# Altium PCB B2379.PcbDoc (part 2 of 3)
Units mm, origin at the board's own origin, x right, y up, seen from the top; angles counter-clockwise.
Board outline 50 x 95 mm, 4 copper layers (Top Layer 1 Signal, Layer 2, Layer 3, Bottom Layer 4 Signal), stack 1.536 mm thick; 177 components, 121 nets, 523 pads, 969 vias.
Unrouted connection lines stored in the file: 25.
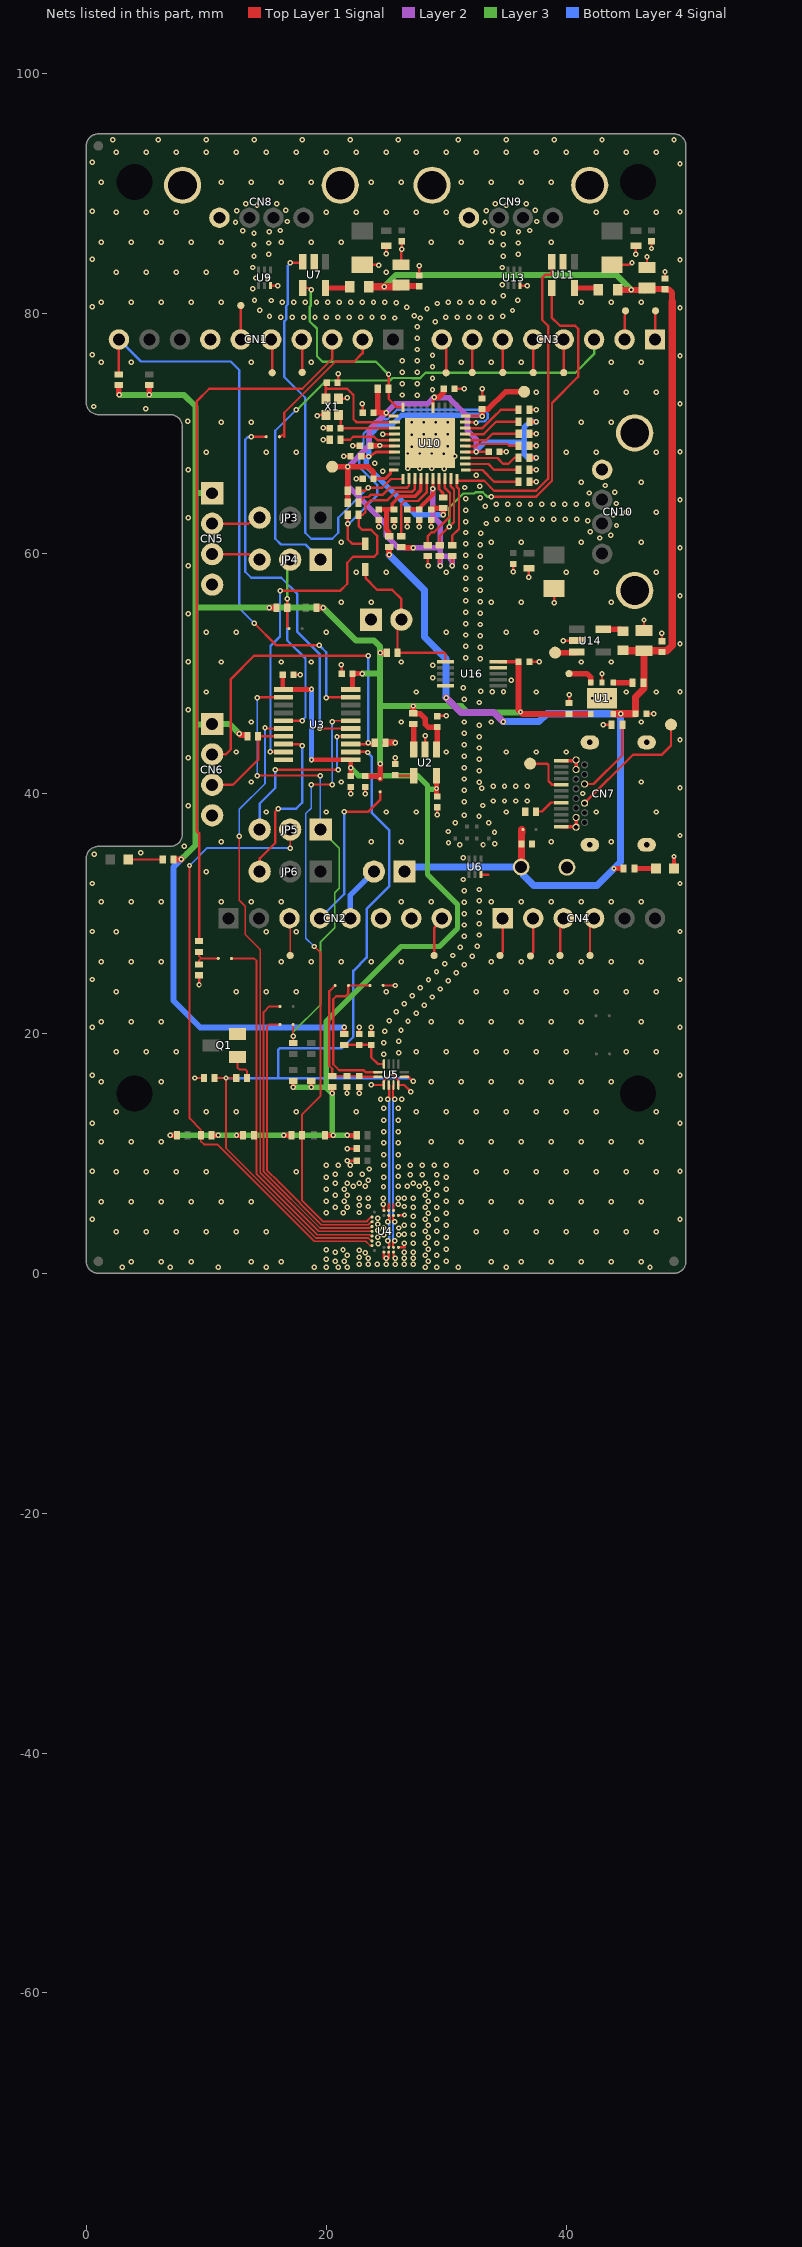
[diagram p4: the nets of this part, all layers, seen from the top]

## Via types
v1: diameter 0.45, hole 0.2, Top Layer 1 Signal to Bottom Layer 4 Signal, tented both sides, 933 vias
v2: diameter 0.45, hole 0.2, Top Layer 1 Signal to Bottom Layer 4 Signal, tented bottom, 24 vias
v3: diameter 0.45/0/0/0.45 (per signal layer), hole 0.2, Top Layer 1 Signal to Bottom Layer 4 Signal, tented both sides, 12 vias

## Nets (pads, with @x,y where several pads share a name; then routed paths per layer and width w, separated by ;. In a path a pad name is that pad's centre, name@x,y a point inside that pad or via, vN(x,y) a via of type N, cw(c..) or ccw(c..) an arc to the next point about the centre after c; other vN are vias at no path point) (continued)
+1V8: C4.2 C7.1 C9.2 R3.1 R17.2 R19.2 R20.2 R24.1 R35.2 R36.2 R37.2 R39.2 U2.5 U3.1 U3.11 | length 83.4
  Top Layer 1 Signal w0.4: v1(7,11.5) R35.2@7.55,11.5 ; R36.2@10.45,11.5 v1(11,11.5) ; v1(12.525,11.5) R3.1@13.08,11.5 ; C9.2@16.375,49.9 16.375,48.675 18.736,48.675 18.761,48.7 v1(18.775,48.7) ; v1(16.465,11.5) R37.2@17.093,11.5 ; v1(17.25,15.5) R20.2@17.25,16.05 ; v1(18.75,15.5) R17.2@18.75,16.05 ; v1(18.775,42.825) U3.11@22.05,42.825 v1(22.05,42.138) C7.1@22.05,41.45 ; R39.2@19.923,11.466 19.958,11.5 v1(20.575,11.5) ; v1(20.5,15) R19.2@20.5,15.55 ; v1(21.75,11.5) R24.1@22.55,11.5
  Top Layer 1 Signal w0.45: U2.5@29.2,41.475 v1(29.2,40.425) 29.2,39.785 C4.2@29.25,39.755
  Layer 3 w0.45: v1(7,11.5) v1(21.75,11.5) ; v1(17.25,15.5) v1(18.75,15.5) 20,15.5 ; v1(20.575,11.5) 20.575,11.514 20.5,11.589 v1(20.5,15) 20,15.5 ; v1(22.05,42.138) 22.688,41.5 27.619,41.5 28.444,40.675 28.444,40.363 ; v1(29.2,40.425) 29.186,40.425 29.124,40.363 28.444,40.363 ; 20,15.5 20,21 26.25,27.25 29.435,27.25 30.948,28.764 30.948,30.745 28.444,33.25 28.444,40.363
  Bottom Layer 4 Signal w0.45: v1(18.775,42.825) v1(18.775,48.7)
+3V3: C2.2 C3.2 C6.2 C8.2 C43.2 CN5.1 CN6.1 R2.1 R7.1 R9.2 R10.2 R11.2 R12.2 R16.2 R18.2 R58.2 R59.2 R60.2 U1.4 U2.1 U3.20 U16.10 | length 146.7
  Top Layer 1 Signal w0.3: U16.10@34.35,51 C43.2@36.05,51
  Top Layer 1 Signal w0.4: R18.2@21.5,19.95 v1(21.5,20.5) ; U3.20@22.05,48.675 22.2,48.675 C8.2@22.2,50 v1(23,50)
  Top Layer 1 Signal w0.45: R11.2@2.72,74.05 2.72,73.28 v1(2.75,73.25) ; v1(5.25,73.25) 5.26,73.26 R12.2@5.26,74.05 ; v1(15.25,55.5) R58.2@15.85,55.5 ; R59.2@19.2,55.5 v1(19.75,55.5) ; C6.2@23.25,41.45 24.3,41.45 R2.1@24.5,41.25 v1(24.5,42.5) ; v1(24.5,51.75) R60.2@25.05,51.75 ; v1(27.25,47.299) R7.1@27.25,46.7 27.28,46.67 27.83,46.67 28.211,46.289 28.25,46.25 28.25,45.784 28.514,45.52 29.22,45.52 C3.2@29.25,45.55 29.25,45.52 29.25,43.725 U2.1@29.2,43.675
  Top Layer 1 Signal w0.5: R16.2@7.275,34.5 7.275,34.515 7.28,34.52 7.92,34.52 v1(7.925,34.525) ; v1(12.75,45) 12.87,44.88 13.395,44.88 13.425,44.85 R9.2@13.425,44.775 ; R10.2@24.949,44.25 v1(25.75,44.25) ; C43.2@36.05,51 36.05,46.95 v1(36.2,46.8) 36.35,46.65 C2.2@40.25,46.65 ; C2.2@40.263,46.65 U1.4@42.05,46.65
  Layer 3 w0.5: v1(2.75,73.25) v1(5.25,73.25) 8.14,73.25 9.102,72.288 9.102,35.701 8.399,34.998 8.398,34.998 v1(7.925,34.525) ; 9.223,45.75 10.44,45.75 CN6.1@10.5,45.81 11.94,45.81 v1(12.75,45) ; 9.223,65.046 10.494,65.046 CN5.1@10.5,65.04 ; 9.223,55.5 v1(15.25,55.5) v1(19.75,55.5) 22.5,52.75 24,52.75 24.5,52.25 v1(24.5,51.75) 24.5,50 ; v1(23,50) 24.5,50 ; v1(24.5,42.5) 24.5,44.125 ; v1(25.75,44.25) 24.625,44.25 24.5,44.125 ; v1(36.2,46.8) 36.15,46.75 31.814,46.75 31.265,47.299 v1(27.25,47.299) 24.502,47.299 24.5,47.297 ; 24.5,44.125 24.5,47.297 ; 24.5,47.297 24.5,50
  Bottom Layer 4 Signal w0.5: v1(7.925,34.525) 7.25,33.85 7.25,22.75 9.5,20.5 v1(21.5,20.5)
+5V: C1.2 C10.2 C17.2 C18.2 C21.2 C22.2 C39.2 C40.2 JP1.1 L1.1 L2.1 L3.1 R1.1 R14.2 R21.2 R57.1 TP18.1 U1.6 | length 138.1
  Top Layer 1 Signal w0.45: v1(44,33.75) R21.2@44.8,33.75
  Top Layer 1 Signal w0.5: v1(25.25,59.9) R57.1@25.25,60.55 ; C17.2@26.15,82.3 C18.2@27.75,82.3 ; L2.1@44.3,82 v1(45.45,82) C21.2@46.6,82 ; C21.2@46.75,82.15 46.85,82.05 C22.2@48.25,82.05 48.255,82.045 48.555,82.045 48.848,81.752 48.848,81
  Top Layer 1 Signal w0.6: L1.1@23.55,82.25 v1(24.825,82.25) 26.1,82.25 C17.2@26.15,82.3 ; TP18.1@36.25,33.875 36.275,33.9 C10.2@36.275,35.8 36.275,36.7 36.3,36.725 R14.2@36.3,37 ; U1.6@43.95,46.65 v1(44.55,46.65) 45.1,46.65 ; L3.1@44.75,51.95 44.8,51.9 C39.2@46.5,51.9 ; 45.101,46.65 C1.2@45.8,46.65 45.8,48.05 46.5,48.75 C39.2@46.5,51.9 ; C21.2@46.6,82 C21.2@46.75,82.15 ; 48.848,81 48.848,52.348 48.4,51.9 C39.2@46.5,51.9
  Layer 2 w0.6: v1(30,48) 31.25,46.75 34,46.75 v1(34.75,46)
  Layer 3 w0.5: v1(24.825,82.25) 25.825,83.25 44.2,83.25 v1(45.45,82)
  Bottom Layer 4 Signal w0.6: v1(25.25,59.9) 28.191,56.959 28.191,53.059 30,51.25 v1(30,48) ; JP1.1@26.52,33.5 26.895,33.875 TP18.1@36.25,33.875 36.403,33.722 36.403,33.222 37.3,32.325 42.575,32.325 v1(44,33.75) 44.55,34.3 v1(44.55,46.65) 38.4,46.65 37.75,46 v1(34.75,46)
CC1_3: CN7.A5 R13.2 | length 2.4
  Top Layer 1 Signal w0.19: R13.2@37.5,38.5 38,38.5 38.75,39.25 CN7.A5@39.59,39.25
CC2_3: CN7.B5 R15.2 | length 6.7
  Top Layer 1 Signal w0.2: CN7.B5@41.55,40.8 42.3,40.8 44.7,43.2 R15.2@44.7,45.75
CFG_SCL_1V8_ST60_3: R26.2 U4.E1 | length 23.7
  Top Layer 1 Signal w0.15: 16,20.75 15.25,20.75 15.054,20.554 15.054,8.599 16.076,7.576 19.599,4.054 23.516,4.054 23.689,4.227 23.725,4.227 23.798,4.3 U4.E1@23.825,4.3
CFG_SDA_1V8_ST60_3: R27.2 U4.F1 | length 25.9
  Top Layer 1 Signal w0.15: R27.2@16.15,22.25 15.25,22.25 14.777,21.777 14.777,8.484 19.484,3.777 23.639,3.777 23.689,3.827 23.725,3.827 23.798,3.9 U4.F1@23.825,3.9
eUSB_ST60_3_N: U4.C5 U4.L5 U5.3 | length 14.3
  Top Layer 1 Signal w0.19: v3@25.573,2.694 25.573,2.211 U4.L5@25.615,2.17 ; v3@25.573,4.3 25.573,4.79 25.614,4.83 U4.C5@25.615,4.83 ; U5.3@25.615,15.7 ccw(c25.615,15.659) 25.573,15.659 25.573,14.63 ccw(c25.704,14.63) v3(25.704,14.5)
  Bottom Layer 4 Signal w0.19: v3@25.574,2.7 25.574,14.37 cw(c25.704,14.37) v3(25.704,14.5)
  other v3: 25.704,2.7 25.704,4.3
eUSB_ST60_3_P: U4.C4 U4.L4 U5.2 | length 14.2
  Top Layer 1 Signal w0.19: v3(25.127,14.5) ccw(c25.127,14.63) 25.257,14.63 25.257,15.659 ccw(c25.215,15.659) U5.2@25.215,15.7 ; U4.L4@25.215,2.17 25.215,2.212 25.256,2.254 v3@25.256,2.694 ; U4.C4@25.215,4.83 25.216,4.83 25.257,4.79 v3@25.257,4.3
  Bottom Layer 4 Signal w0.19: v3(25.127,14.5) cw(c25.127,14.37) 25.257,14.37 v3@25.257,2.743
  other v3: 25.127,2.7 25.127,4.3
EXT_RX_3V3_4: CN5.3 JP4.3 | length 4.2
  Top Layer 1 Signal w0.2: CN5.3@10.5,59.96 13.554,59.96 14.014,59.5 JP4.3@14.46,59.5
EXT_SCL_1V8_4: JP5.3 U3.14 | length 14.8
  Top Layer 1 Signal w0.2: v1(15.75,42) v1(21,42) ; v1(20.902,44.725) 20.952,44.775 U3.14@22.05,44.775
  Bottom Layer 4 Signal w0.2: JP5.3@14.46,37 14.46,39.171 15.75,40.461 v1(15.75,42) ; v1@20.927,44.7 v1(20.902,44.725) 20.902,42.098 v1(21,42)
EXT_SCL_3V3_4: CN6.3 R9.1 U3.7 | length 8.8
  Top Layer 1 Signal w0.2: CN6.3@10.5,40.73 12.23,40.73 14.325,42.825 R9.1@14.325,44.775 U3.7@16.45,44.775
EXT_SDA_1V8_4: JP6.3 U3.8 | length 14.4
  Top Layer 1 Signal w0.2: JP6.3@14.46,33.5 14.471,33.511 14.471,34.608 15.75,35.887 15.75,38.5 v1(16,38.75) ; U3.8@16.45,44.125 17.875,44.125 v1(18,44)
  Bottom Layer 4 Signal w0.2: v1(16,38.75) 17.5,38.75 18,39.25 v1(18,44)
EXT_SDA_3V3_4: CN6.2 R10.1 U3.13 | length 29.1
  Top Layer 1 Signal w0.2: CN6.2@10.5,43.27 11.63,43.27 12.05,43.69 12.05,49.55 14,51.5 v1(23.5,51.5) ; U3.13@22.05,44.125 23.924,44.125 R10.1@24.049,44.25
  Bottom Layer 4 Signal w0.2: v1(23.5,44.25) v1(23.5,51.5)
EXT_TX_3V3_4: CN5.2 JP3.3 | length 4.2
  Top Layer 1 Signal w0.2: CN5.2@10.5,62.5 13.518,62.5 14.018,63 JP3.3@14.46,63
GND: C1.1 C2.1 C3.1 C4.1 C5.1 C6.1 C7.2 C8.1 C9.1 C10.1 C11.1 C12.2 C13.2 C14.2 C15.1 C16.2 C17.1 C18.1 C19.1 C20.1 C21.1 C22.1 C23.1 C24.1 C25.1 C26.1 C27.1 C28.1 C29.1 C30.1 C31.1 C32.1 C33.1 C34.1 C35.1 C36.1 C37.1 C38.1 C39.1 C40.1 C41.1 C42.1 C43.1 CN1.7 CN2.6 CN2.7 CN5.4 CN6.4 CN7.A1 CN7.A12 CN7.B1 CN7.B12 CN7.SH1 CN7.SH2 CN7.SH3 CN7.SH4 CN8.4 CN8.5 CN8.6 CN9.4 CN9.5 CN9.6 CN10.4 CN10.5 CN10.6 H1.1 H2.1 H3.1 H4.1 JP2.1 LD2.2 Q1.2 R6.1 R13.1 R15.1 R28.2 R38.1 R42.1 R43.1 R44.1 R45.1 R46.1 R47.1 R54.2 TP20.1 U1.2 U1.EP U2.2 U3.10 U4.A3 U4.A4 U4.A5 U4.C6 U4.L6 U4.N3 U4.N4 U4.N5 U5.1 U5.4 U6.3 U7.2 U8.2 U9.3 U10.34 U10.41 U11.2 U12.2 U13.3 U14.2 U15.2 U16.5 U16.9 X1.2 X1.4 | length 61.5
  Top Layer 1 Signal w0.2: v1(9.035,16.285) R38.1@9.8,16.285 ; v1(9.4,24.052) R6.1@9.4,24.852 ; U9.3@15.35,82.35 v1@15.95,82.35 ; C9.1@17.275,49.9 v1(17.825,49.9) ; v1(19.25,71.5) 19.325,71.575 X1.4@19.975,71.575 ; v1(19.75,69.5) R54.2@20.3,69.5 ; v1(19.75,70.5) 19.78,70.47 C25.1@20.3,70.47 ; C26.1@20.95,74.25 21,74.3 v1(21,75) ; X1.2@21.025,72.925 21.675,72.925 v1(21.75,73) ; v1(21.25,50.75) 21.25,50.682 21.3,50.632 C8.1@21.3,50 ; v1(21.465,68.134) 21.474,68.125 C29.1@22.025,68.125 ; v1(21.735,15) C12.2@21.735,15.55 ; v1(21.75,9.375) C15.1@22.55,9.375 ; v1(21.75,10.4) C16.2@22.55,10.4 ; v1@22,40 22.05,40.05 C7.2@22.05,40.55 ; v1(22.225,69) C30.1@22.8,69 ; v1(22.5,66.25) C31.1@23.05,66.25 ; v1(22.75,15) C14.2@22.75,15.55 ; C13.2@22.75,19.95 v1(22.75,20.525) ; v1(23,72.5) 23,72.432 23.05,72.382 C32.1@23.05,71.75 ; C19.1@23,84.1 23.755,84.1 24.25,84.1 cw(c24.25,83.9) v1(24.38,84.052) ; v1(23.25,40) C6.1@23.25,40.55 ; C11.1@23.75,19.95 v1(23.75,20.525) ; v1(23.765,15.708) 24.314,15.7 ccw(c24.316,15.9) 24.316,15.7 U5.1@24.815,15.7 24.815,16.062 25.08,16.327 25.09,16.327 v1(25.474,16.712) 25.888,16.298 25.888,16.24 26.015,16.113 U5.4@26.015,15.7 26.515,15.7 v1(27.065,15.15) ; v1(24.375,62.25) 24.383,62.258 24.383,62.792 C38.1@24.39,62.8 ; v1(24.708,69.975) U10.34@25.7,69.975 ; R28.2@24.75,24 v1(25.75,24) ; v1@24.815,1.241 U4.N3@24.815,1.77 ; U4.A3@24.815,5.23 v1@24.815,5.759 ; v1(25,85) U8.2@25,85.675 ; v1@25.215,1.241 U4.N4@25.215,1.77 ; U4.A4@25.215,5.23 25.215,5.758 ; v1@25.615,1.241 U4.N5@25.615,1.77 ; U4.A5@25.615,5.23 25.615,5.758 ; C37.1@25.65,62.8 25.662,62.788 25.662,62.263 v1(25.675,62.25) ; C5.1@25.75,42.45 v1(25.75,43) ; U4.L6@26.015,2.17 26.543,2.17 ; U4.C6@26.015,4.83 v1@26.543,4.83 ; C17.1@26.25,84.1 26.25,85.257 26.3,85.307 v1(26.3,85.375) C20.1@26.3,86.05 ; v1(26.75,62.25) C35.1@26.75,62.8 ; v1(27.75,62.25) C36.1@27.75,62.8 ; C18.1@27.75,83.2 v1(27.75,84) ; U2.2@28.25,43.675 v1(28.25,44.825) ; R44.1@28.475,59.8 28.475,59.025 v1(28.5,59) ; v1(28.75,62.25) C27.1@28.75,62.8 ; v1(29.25,38.23) C4.1@29.25,38.855 ; C3.1@29.25,46.45 29.3,46.5 v1(30,46.5) ; C33.1@30.7,73.75 v1(31.5,73.75) ; U6.3@32.896,33.24 33.495,33.24 33.496,33.241 ; C28.1@33,72.95 v1(33,73.75) ; C34.1@34.45,68.5 v1(35,68.5) ; v1(35.6,58.5) C42.1@35.6,59.15 ; U13.3@36.15,82.35 36.746,82.35 v1(36.75,82.354) ; v1(36.9,58.025) U15.2@36.9,58.775 ; C43.1@36.95,51 v1(37.75,51) ; R45.1@36.95,66 v1(37.5,66) ; R42.1@36.95,67 v1(37.5,67) ; R46.1@36.95,69 v1(37.5,69) ; R47.1@36.95,72 v1(37.5,72) ; R43.1@36.954,70.003 37.497,70.003 v1(37.5,70) ; v1(39,55.925) C41.1@39,57.1 ; v1(39.775,52.75) U14.2@40.9,52.75 ; C2.1@40.25,47.55 v1(40.25,48.25) ; CN7.B12@40.79,37.25 CN7.B12@40.84,37.2 ; U1.2@43,49.25 v1(43,50) ; v1(43.1,45.75) R15.1@43.8,45.75 ; C23.1@43.825,84.1 45.282,84.1 45.432,84.25 v1(45.5,84.25) ; v1(45.825,84.975) U12.2@45.825,85.675 ; C39.1@46.5,53.6 v1(46.5,54.475) ; C1.1@46.7,46.65 v1(47.325,46.65) ; C21.1@46.75,83.85 v1(46.75,84.75) ; v1(47.125,85.45) C24.1@47.125,86.05 ; v1(47.975,53.375) 48,53.35 C40.1@48,52.7 ; C22.1@48.25,82.95 v1(48.25,83.5)
  Top Layer 1 Signal w0.3: CN7.A1@39.59,37.25 CN7.B12@40.79,37.25 ; CN7.A12@39.59,42.75 40.79,42.75 CN7.B1@40.84,42.8 CN7.B1@40.84,42 ; CN7.B12@40.84,37.2 CN7.B12@40.84,38 ; LD2.2@49,33.75 v1(49,34.75)
  other v1: 3,0.5 7,0.5 11,0.5 15,0.5 19,0.5 19.998,0.505 21,0.5 21.75,0.5 28.25,0.5 29.215,0.5 31,0.5 35,0.5 47,0.5 22.75,0.75 23.5,0.75 24.25,0.75 25,0.75 25.75,0.75 26.5,0.75 27.25,0.75 3.758,0.967 6.258,0.967 8.758,0.967 13.758,0.967 16.258,0.967 33.758,0.967 36.258,0.967 38.758,0.967 41.258,0.967 43.758,0.967 46.258,0.967 20.75,1 21.5,1 28.5,1 30,1 20,1.169 23.5,1.25 25,1.25 25.75,1.25 26.5,1.25 27.25,1.25 22.75,1.35 21.75,1.5 28.25,1.5 29.215,1.5 23.248,1.705 20.75,1.75 26.5,1.75 27.25,1.75 22.75,1.925 19.998,1.953 21.4,1.95 28.5,2 30,2 24.325,2.475 26.5,2.5 27.25,2.5 28.25,2.5 29.215,2.508 24.3,3 28.5,3 30,3 24.8,3.2 26.05,3.2 26.5,3.25 27.25,3.25 2.508,3.467 5.008,3.467 7.508,3.467 10.008,3.467 12.508,3.467 15.008,3.467 32.508,3.467 35.008,3.467 37.508,3.467 40.008,3.467 42.508,3.467 45.008,3.467 47.508,3.467 28.25,3.5 29.215,3.5 24.3,3.6 24.805,3.779 26.045,3.779 26.5,4 27.25,4 28.5,4 30,4 24.3,4.1 0.5,4.5 28.25,4.5 29.215,4.5 49.5,4.5 24.3,4.6 27.25,4.75 26.532,4.865 28.5,5 30,5 19.998,5.042 21.425,5.05 22.748,5.073 20.75,5.5 21.75,5.5 27.25,5.5 28.25,5.5 29.215,5.5 23.5,5.575 26.5,5.575 22.75,5.675 24.75,5.75 26.025,5.75 1.258,5.967 3.758,5.967 6.258,5.967 8.758,5.967 11.258,5.967 13.758,5.967 31.258,5.967 33.758,5.967 36.258,5.967 38.758,5.967 41.258,5.967 43.758,5.967 46.258,5.967 20,6 21.5,6 28.5,6 30,6 22.75,6.25 23.5,6.25 24.75,6.25 26.025,6.25 26.5,6.25 27.25,6.25 20.75,6.5 21.75,6.5 28.25,6.5 29.215,6.5 20,7 21.5,7 28.5,7 30,7 24.775,7.225 22.25,7.25 23.25,7.25 26.025,7.25 26.75,7.25 27.75,7.25 20.75,7.5 21.75,7.5 22.75,7.5 27.25,7.5 28.25,7.5 29.215,7.5 23.5,7.75 20,8 24.8,8 30,8 26.025,8.1 27,8.225 28,8.225 29.215,8.225 20.75,8.25 22,8.25 23,8.25 2.508,8.467 5.008,8.467 7.508,8.467 10.008,8.467 17.508,8.467 32.508,8.467 35.008,8.467 37.508,8.467 40.008,8.467 42.508,8.467 45.008,8.467 47.508,8.467 0.5,8.5 49.5,8.5 23.6,8.7 26.025,8.9 20,9 21,9 22,9 24.8,9 27,9 28,9 29,9 30,9 24.8,9.9 26.025,9.9 24.8,10.9 26.025,10.9 1.258,10.967 3.758,10.967 6.258,10.967 28.758,10.967 31.258,10.967 33.758,10.967 36.258,10.967 38.758,10.967 41.258,10.967 43.758,10.967 46.258,10.967 24.8,11.8 26.025,11.8 0.5,12.5 49.5,12.5 24.8,12.75 26.025,12.75 2.508,13.467 7.508,13.467 10.008,13.467 12.508,13.467 17.508,13.467 22.508,13.467 27.508,13.467 30.008,13.467 32.508,13.467 35.008,13.467 37.508,13.467 40.008,13.467 42.508,13.467 47.508,13.467 24.8,13.75 26.025,13.75 24.53,14.5 26.3,14.5 1.258,15.967 6.258,15.967 28.758,15.967 31.258,15.967 33.758,15.967 36.258,15.967 38.758,15.967 41.258,15.967 43.758,15.967 0.5,16.5 49.5,16.5 24.795,18.273 26.035,18.391 2.508,18.467 5.008,18.467 7.508,18.467 27.508,18.467 30.008,18.467 32.508,18.467 35.008,18.467 37.508,18.467 40.008,18.467 45.008,18.467 47.508,18.467 24.795,19.223 26.035,19.341 24.899,20.167 26.241,20.268 0.5,20.5 49.5,20.5 1.258,20.967 3.758,20.967 6.258,20.967 28.758,20.967 31.258,20.967 33.758,20.967 36.258,20.967 38.758,20.967 41.258,20.967 46.258,20.967 26.821,21.02 25.256,21.047 27.493,21.692 25.842,21.795 28.165,22.364 26.514,22.467 28.837,23.035 27.185,23.138 2.508,23.467 12.508,23.467 15.008,23.467 17.508,23.467 25.008,23.467 32.508,23.467 35.008,23.467 37.508,23.467 40.008,23.467 42.508,23.467 45.008,23.467 47.508,23.467 29.508,23.707 27.857,23.81 30.18,24.379 0.5,24.5 28.529,24.482 49.5,24.5 30.852,25.051 29.201,25.154 31.524,25.722 29.872,25.825 1.258,25.967 3.758,25.967 6.258,25.967 16.258,25.967 18.758,25.967 21.258,25.967 23.758,25.967 26.258,25.967 33.758,25.967 36.258,25.967 38.758,25.967 41.258,25.967 43.758,25.967 46.258,25.967 32.164,26.424 30.544,26.497 31.187,27.196 32.599,27.269 31.506,28.091 32.761,28.205 2.508,28.467 15.008,28.467 17.508,28.467 0.5,28.5 49.5,28.5 31.525,29.041 32.766,29.155 31.525,29.991 32.766,30.105 31.525,30.941 1.258,30.967 3.758,30.967 6.258,30.967 11.258,30.967 13.758,30.967 16.258,30.967 26.258,30.967 28.758,30.967 33.758,30.967 36.258,30.967 38.758,30.967 41.258,30.967 43.758,30.967 46.258,30.967 32.766,31.055 31.525,31.891 32.766,32.005 0.5,32.5 49.5,32.5 31.433,32.837 10.008,33.467 31.412,34.661 0.675,34.95 4.525,35.075 8.15,35.6 31.139,35.728 33.079,35.746 34.053,35.821 30.202,35.886 11.258,35.967 23.758,35.967 26.258,35.967 38.758,35.967 43.758,35.967 49.5,36.5 34.035,36.771 30.188,36.836 33.538,37.581 30.776,37.583 32.745,38.104 31.505,38.192 15.008,38.467 20.008,38.467 25.008,38.467 27.508,38.467 35.008,38.467 42.508,38.467 47.508,38.467 8.5,39 33.039,39.007 31.517,39.313 33.913,39.38 34.863,39.38 35.813,39.38 36.763,39.38 22.05,40 41.403,40.003 31.517,40.263 32.985,40.447 49.5,40.5 33.92,40.62 34.87,40.62 35.82,40.62 36.77,40.62 32.758,40.947 13.758,40.967 21.258,40.967 46.258,40.967 31.517,41.213 32.758,41.897 31.517,42.163 32.758,42.847 8.5,43 31.517,43.113 12.508,43.467 30.008,43.467 35.008,43.467 37.508,43.467 40.008,43.467 32.758,43.797 31.517,44.063 49.5,44.5 32.758,44.747 31.517,45.013 32.758,45.697 31.517,45.963 13.758,45.967 26.258,45.967 33.758,45.967 46.258,45.967 8.5,47 32.758,47.597 31.517,47.863 10.008,48.467 27.508,48.467 37.508,48.467 45.008,48.467 47.508,48.467 33.835,48.491 34.785,48.491 49.5,48.5 32.886,48.538 31.415,48.808 35.434,49.451 28.87,49.672 28.877,50.704 11.258,50.967 16.258,50.967 18.758,50.967 26.258,50.967 41.258,50.967 43.758,50.967 8.5,51 32.862,51.243 31.621,51.318 32.862,52.193 31.621,52.268 49.5,52.5 32.862,53.143 31.621,53.218 10.008,53.467 12.508,53.467 20.008,53.467 30.008,53.467 35.008,53.467 37.508,53.467 32.862,54.093 31.621,54.168 8.5,55 32.862,55.043 31.621,55.118 21.258,55.967 23.758,55.967 33.758,55.967 36.258,55.967 43.758,55.967 32.862,55.993 31.621,56.068 49.5,56.5 32.862,56.943 31.621,57.018 32.862,57.893 31.621,57.968 22.508,58.467 25.008,58.467 30.008,58.467 40.008,58.467 42.508,58.467 47.508,58.467 32.862,58.843 31.621,58.918 8.5,59 32.862,59.793 31.621,59.868 49.5,60.5 32.862,60.743 31.621,60.818 21.258,60.967 33.758,60.967 36.258,60.967 41.258,60.967 46.258,60.967 42.807,61.307 43.731,61.53 32.884,61.693 31.636,61.768 42.008,61.82 44.21,62.35 33.352,62.52 31.621,62.669 41.824,62.752 34.233,62.876 35.182,62.88 36.132,62.88 37.082,62.88 38.032,62.88 38.982,62.88 39.932,62.88 40.882,62.88 8.5,63 43.948,63.263 45.008,63.467 47.508,63.467 31.621,63.619 33.254,63.95 34.189,64.12 35.139,64.12 36.089,64.12 37.039,64.12 37.989,64.12 38.939,64.12 39.889,64.12 40.839,64.12 41.789,64.12 44.179,64.185 49.5,64.5 31.621,64.569 32.862,64.677 41.933,65.059 44.048,65.126 31.561,65.517 32.805,65.625 43.279,65.684 41.258,65.967 46.258,65.967 32.503,66.526 24.703,66.861 8.5,67 24.041,67.542 10.008,68.467 15.008,68.467 17.508,68.467 40.008,68.467 42.508,68.467 47.508,68.467 49.5,68.5 11.258,70.967 13.758,70.967 41.258,70.967 43.758,70.967 8.45,71.05 4.95,72.1 0.625,72.275 49.5,72.5 26.356,73.228 27.596,73.225 37.508,73.467 42.508,73.467 45.008,73.467 47.508,73.467 28.862,73.685 26.356,74.178 27.596,74.175 28.862,74.635 26.356,75.128 27.596,75.125 28.862,75.585 1.258,75.967 3.758,75.967 13.758,75.967 18.758,75.967 31.258,75.967 33.758,75.967 36.258,75.967 43.758,75.967 46.258,75.967 26.356,76.078 27.596,76.075 49.5,76.5 28.862,76.535 0.5,76.575 27.596,77.025 27.596,77.975 27.591,78.925 29.1,79.354 25.715,79.65 27.834,79.656 16.217,79.721 17.167,79.721 18.117,79.721 19.067,79.721 20.017,79.721 20.967,79.721 21.917,79.721 22.867,79.721 23.817,79.721 24.767,79.721 29.976,79.721 30.926,79.721 31.876,79.721 32.826,79.721 33.776,79.721 15.27,79.794 34.724,79.788 27.341,79.841 35.537,80.279 14.463,80.295 28.41,80.411 49.5,80.5 0.5,80.575 26.719,80.559 29.245,80.864 25.844,80.929 16.345,80.962 17.295,80.962 18.245,80.962 19.195,80.962 20.145,80.962 21.095,80.962 22.045,80.962 22.995,80.962 23.945,80.962 24.895,80.962 30.19,80.962 31.14,80.962 32.09,80.962 33.04,80.962 33.99,80.962 1.258,80.967 3.758,80.967 6.258,80.967 8.758,80.967 11.258,80.967 41.258,80.967 43.758,80.967 46.258,80.967 15.406,81.111 14.023,81.137 35.978,81.121 34.778,81.491 13.866,82.074 15.95,82.35 34.666,82.435 14.123,82.989 15.112,82.982 2.508,83.467 5.008,83.467 7.508,83.467 10.008,83.467 12.508,83.467 25.008,83.467 13.866,83.865 34.666,83.865 49.5,84.5 0.5,84.55 13.98,84.808 34.78,84.808 15.22,84.952 36.02,84.952 13.98,85.758 34.78,85.758 15.22,85.902 36.02,85.902 1.258,85.967 3.758,85.967 6.258,85.967 8.758,85.967 11.258,85.967 16.258,85.967 18.758,85.967 21.258,85.967 28.758,85.967 31.258,85.967 33.758,85.967 38.758,85.967 13.98,86.708 34.78,86.708 15.238,86.852 36.038,86.852 13.055,86.927 33.855,86.927 16.183,86.947 36.983,86.947 12.44,87.651 33.24,87.651 16.769,87.695 37.569,87.695 2.508,88.467 5.008,88.467 7.508,88.467 20.008,88.467 22.508,88.467 25.008,88.467 27.508,88.467 30.008,88.467 42.508,88.467 45.008,88.467 47.508,88.467 49.5,88.5 0.5,88.55 12.539,88.596 33.339,88.596 16.638,88.636 37.438,88.636 14.229,89.046 35.029,89.046 13.289,89.18 15.869,89.194 34.089,89.18 36.669,89.194 1.258,90.967 11.258,90.967 13.758,90.967 16.258,90.967 18.758,90.967 23.758,90.967 26.258,90.967 31.258,90.967 33.758,90.967 36.258,90.967 38.758,90.967 49.5,92.5 0.5,92.625 2.508,93.467 5.008,93.467 7.508,93.467 10.008,93.467 12.508,93.467 15.008,93.467 17.508,93.467 20.008,93.467 22.508,93.467 25.008,93.467 27.508,93.467 30.008,93.467 32.508,93.467 35.008,93.467 37.508,93.467 40.008,93.467 42.508,93.467 45.008,93.467 47.508,93.467 2.2,94.5 6,94.5 10,94.5 14,94.5 18,94.5 22,94.5 26,94.5 31,94.5 35,94.5 39,94.5 43,94.5 49,94.5
  other v2: 42.2,47.95 42.975,47.95 43.75,47.95 29.85,67.077 26.8,67.1 27.8,67.1 28.8,67.1 30.725,68.125 29.802,68.323 26.8,68.35 27.8,68.35 28.8,68.35 27.125,68.923 28.125,68.975 29.125,68.975 30.125,68.975 27.125,69.923 28.125,69.975 29.125,69.975 30.125,69.975 27.125,70.975 28.125,70.975 29.125,70.975 30.125,70.975
HUB_+1V5: C27.2 C28.2 C29.2 R56.1 TP23.1 U10.20 U10.37 | length 31.4
  Top Layer 1 Signal w0.25: C29.2@22.925,68.125 22.95,68.1 v1(23.563,68.1) ccw(c23.563,68.35) 23.709,68.147 24.188,68.493 24.813,68.493 24.831,68.475 U10.37@25.7,68.475 ; U10.20@31.65,71.475 v1(33.019,71.475)
  Top Layer 1 Signal w0.35: C28.2@33,72.05 C28.2@33.019,71.97
  Top Layer 1 Signal w0.45: C27.2@28.75,63.7 28.775,63.7 28.875,63.8 R56.1@29.75,63.8 v1(29.75,63.25) ; C28.2@33,72.05 33.5,72.05 34.95,73.5 TP23.1@36.5,73.5 ; v1(33.019,71.475) C28.2@33.019,71.97
  Bottom Layer 4 Signal w0.45: v1(29.75,63.25) 27.44,63.25 23.327,67.363 23.327,67.864 v1(23.563,68.1) 23.563,69.813 24.5,70.75 25.5,70.75 26.302,71.552 32.942,71.552 v1(33.019,71.475)
HUB_+3V3: C30.2 C31.2 C32.2 C33.2 C34.2 C35.2 C36.2 R40.2 R41.2 R48.2 R49.2 R50.2 R52.1 R53.2 R55.2 TP22.1 U10.6 U10.14 U10.25 U10.31 U10.36 U10.40 | length 73.6
  Top Layer 1 Signal w0.2: R40.2@29.475,59.8 29.475,59.025 v1(29.5,59) ; C33.2@29.795,73.745 C33.2@29.8,73.75 ; v1(30.5,59) R50.2@30.5,59.8 ; v1@32.403,68.475 ccw(c32.403,68.675) 32.492,68.496 v1@32.499,68.5
  Top Layer 1 Signal w0.25: C31.2@23.95,66.25 24.925,66.25 25.375,66.7 25.375,66.975 U10.40@25.65,66.975 ; v1@24.555,68.975 U10.36@25.7,68.975 ; v1(25,71.75) 25.275,71.475 U10.31@25.65,71.475 ; v1(28.9,65.399) U10.6@28.9,66.275 ; U10.25@28.9,72.175 v1@28.9,72.882 ; U10.14@31.6,68.475 v1@32.403,68.475 ; v1(32.5,68.5) C34.2@33.55,68.5
  Top Layer 1 Signal w0.35: C36.2@27.75,63.7 27.775,63.7 27.855,63.78 27.855,63.887 28.9,64.932 v1(28.9,65.399) ; R49.2@36.95,68 v1(37.5,68) ; R48.2@36.95,71 v1(37.5,71)
  Top Layer 1 Signal w0.4: C35.2@26.75,63.7 C36.2@27.75,63.7
  Top Layer 1 Signal w0.45: TP22.1@20.5,67.25 23.5,67.25 23.941,66.809 23.941,66.259 C31.2@23.95,66.25 ; R52.1@21.8,64.25 R53.2@21.8,65.25 v1(21.8,67.239) ; C30.2@23.7,69 v1@24.43,69 ; C32.2@23.95,71.75 v1(25,71.75) ; 24.3,71.95 R41.2@24.3,73.75 ; R55.2@26.25,60.55 26.28,60.52 26.567,60.52 26.587,60.5 v1(27.25,60.5) ; v1(29,73.05) 29.4,73.05 29.795,73.445 C33.2@29.795,73.745
  Layer 2 w0.45: v1(24.453,69.023) 23.584,69.023 ; v1(28.9,65.399) 28.9,63.1 29.5,62.5 29.5,60.445 ; v1(29.5,59) 29.5,59.73 ; v1(30.5,59) 30.5,59.45 30.15,59.8 29.57,59.8 29.5,59.73 ; v1(32.5,68.5) 32.5,69.55 31.75,70.3 31.75,71.5 30.25,73 29.05,73 v1(29,73.05) 28.45,72.5 25.75,72.5 v1(25,71.75) 23.584,70.334 23.584,69.023 ; 23.584,69.023 v1(21.8,67.239) 21.8,65.641 25,62.441 25,61.5 26,60.5 v1(27.25,60.5) 29.445,60.5 29.5,60.445 ; 29.5,59.73 29.5,60.445
  Bottom Layer 4 Signal w0.45: v1@32.5,68.555 33.25,69.305 36.5,69.305 ; v1(37.5,68) 36.8,68 36.5,68.3 36.5,69.305 ; v1(37.5,71) 36.975,71 36.5,70.525 36.5,69.305
HUB_+5V: C37.2 C38.2 R57.2 U10.4 | length 7.9
  Top Layer 1 Signal w0.3: C37.2@25.37,63.7 C37.2@25.5,63.7 ; C37.2@25.52,63.805 25.501,64.024 cw(c25.8,64.05) 25.5,64.05 25.5,64.174 26.099,64.773 27.373,64.773 27.864,65.264 ; 27.9,65.264 U10.4@27.9,66.275
  Top Layer 1 Signal w0.4: C38.2@24.39,63.7 25.028,63.7 ; R57.2@25.25,61.45 25.25,61.8 25.028,62.022 25.028,63.7 ; C37.2@25.65,63.7 25.37,63.7 25.028,63.7
HUB_EN: D1.2 JP2.2 R60.1 U16.1 | length 13.7
  Top Layer 1 Signal w0.2: D1.2@23.25,58.68 23.283,58.647 23.283,57.967 24.25,57 25.5,57 26.27,56.23 JP2.2@26.27,54.5 26.27,54.054 25.95,53.734 R60.1@25.95,51.75 29.075,51.75 29.833,51.75 29.95,51.633 U16.1@29.95,51
HUB_RST_6_N: D1.1 R51.2 U10.19 | length 26.8
  Top Layer 1 Signal w0.2: R51.2@21.8,63.25 v1(21.8,62.504) 21.8,61.2 22.18,60.82 D1.1@23.25,60.82 ; U10.19@31.6,70.975 32.375,70.975 32.444,70.975 v1(32.492,70.927)
  Bottom Layer 4 Signal w0.2: v1(21.8,62.504) 21.868,62.504 21.992,62.628 22.018,62.628 24.246,64.856 24.246,65.75 22.75,67.246 22.75,68 23.111,68.361 23.111,70 24,70.889 24,71 24.111,71 24.313,71.202 25.091,71.202 25.893,72.004 33.129,72.004 33.471,71.662 33.471,71.288 33.206,71.023 32.734,71.023 32.686,70.975 32.54,70.975 v1(32.492,70.927)
LED1B_6: R44.2 U10.8 | length 6.6
  Top Layer 1 Signal w0.2: R44.2@28.475,60.7 28.475,61.475 28.798,61.798 29.016,61.798 30.327,63.109 30.327,65.049 29.9,65.476 U10.8@29.9,66.275
LED2B_6: R45.2 U10.11 | length 4.8
  Top Layer 1 Signal w0.2: U10.11@31.65,66.975 32.313,66.975 32.316,66.978 33.022,66.978 34,66 R45.2@36.05,66
LED3B_6: R46.2 U10.15 | length 4.6
  Top Layer 1 Signal w0.2: U10.15@31.6,68.975 32.475,68.975 32.648,69.148 35.102,69.148 35.25,69 R46.2@36.05,69
LED4B_6: R47.2 U10.18 | length 5.1
  Top Layer 1 Signal w0.2: U10.18@31.6,70.475 33.019,70.475 34.192,71.648 34.217,71.648 34.569,72 R47.2@36.05,72
LINK_STATUS_1V8: R34.2 R38.2 U3.12 U4.J1 U5.5 | length 75.8
  Top Layer 1 Signal w0.15: R38.2@10.7,16.285 v1(11.649,16.285) ; R34.2@12.501,16.285 v1(11.649,16.285) ; U4.J1@23.825,2.7 23.798,2.7 23.748,2.75 23.712,2.75 23.516,2.946 19.123,2.946 11.648,10.421 v1(11.649,16.285) v1(11.649,16.285)
  Top Layer 1 Signal w0.2: U3.12@22.05,43.475 23.4,43.475 v1(23.45,43.425) ; U5.5@26.515,16.375 26.875,16.375 v1(27.25,16)
  Bottom Layer 4 Signal w0.2: v1(11.649,16.285) 11.674,16.26 16,16.26 ; v1(23.45,43.425) 23.789,43.086 23.789,38.421 25.25,36.96 25.25,32.25 23.375,30.375 23.375,26.325 22.27,25.22 22.27,19.725 21.295,18.75 16.117,18.75 16,18.633 16,16.26 ; v1(27.25,16) 26.99,16.26 16,16.26
LINK_STATUS_3V3: R51.1 U3.9 U10.3 | length 36.4
  Top Layer 1 Signal w0.2: v1(15.329,43.5) 15.354,43.475 U3.9@16.45,43.475 ; v1(16.175,56.9) 21.15,56.9 21.75,57.5 21.75,59.25 22.25,59.75 24,59.75 24.25,60 24.25,61.5 23.75,62 23,62 22.7,62.3 R51.1@22.7,63.25 23.05,63.25 23.275,63.475 23.275,64.013 23.704,64.441 25.059,64.441 25.767,65.15 27.167,65.15 27.4,65.383 U10.3@27.4,66.275
  Bottom Layer 4 Signal w0.2: v1(15.329,43.5) 15.354,43.525 15.354,52.304 16.15,53.1 16.15,56.875 v1(16.175,56.9)
LPWRM_6: R52.2 U10.2 | length 5.5
  Top Layer 1 Signal w0.2: R52.2@22.7,64.25 22.7,64.345 22.855,64.5 22.95,64.5 23.175,64.725 23.525,64.725 23.7,64.9 24.704,64.9 25.314,65.51 26.746,65.51 26.905,65.669 26.905,66.27 U10.2@26.9,66.275
MODE_INT_1V8: U3.6 U4.G1 | length 51.6
  Top Layer 1 Signal w0.15: v1(12.75,36.433) 12.75,31.113 13.25,30.613 13.25,28.25 14.5,27 14.5,8.369 19.369,3.5 U4.G1@23.825,3.5 ; v1(14.902,45.478) v1@14.955,45.425
  Top Layer 1 Signal w0.2: v1@14.955,45.425 U3.6@16.45,45.425
  Bottom Layer 4 Signal w0.15: v1(12.75,36.433) 12.75,38.677 14.902,40.829 v1(14.902,45.478)
MODE_INT_3V3_4: R5.2 U3.15 | length 32.5
  Top Layer 1 Signal w0.2: v1(13.75,69.75) R5.2@15,69.75 ; v1(19.45,45.45) 19.475,45.425 U3.15@22.05,45.425
  Bottom Layer 4 Signal w0.2: v1(13.75,69.75) 13.704,69.704 13.454,69.704 13.25,69.5 13.25,58.5 13.75,58 16.25,58 17.6,56.65 17.6,53.475 19.45,51.625 v1(19.45,45.45)
NetC5_2: C5.2 U2.4 | length 1.6
  Top Layer 1 Signal w0.2: C5.2@25.75,41.55 25.825,41.475 U2.4@27.3,41.475
NetC11_2: C11.2 C13.1 R18.1 U5.10 | length 4.6
  Top Layer 1 Signal w0.2: R18.1@21.5,19.05 C13.1@22.75,19.05 C11.2@23.75,19.05 23.75,18.015 24.315,17.45 U5.10@24.815,17.45
NetC12_1: C12.1 C14.1 R19.1 R22.1 U5.12 | length 11.7
  Top Layer 1 Signal w0.2: R22.1@20.75,24 20.26,23.51 20.26,17.3 20.5,17.06 R19.1@20.5,16.45 C12.1@21.735,16.45 ; C12.1@21.735,16.45 C14.1@22.75,16.45 22.825,16.375 U5.12@24.315,16.375
NetC25_2: C25.2 U10.33 X1.1 | length 5.7
  Top Layer 1 Signal w0.2: X1.1@21.025,71.575 21.2,71.4 C25.2@21.2,70.47 21.205,70.475 U10.33@25.7,70.475
NetC26_2: C26.2 U10.32 X1.3 | length 9.5
  Top Layer 1 Signal w0.2: X1.3@19.975,72.925 19.975,73.875 ; C26.2@20.05,74.25 19.975,74.175 19.975,73.875 ; U10.32@25.7,70.975 22.514,70.975 22.275,71.214 22.275,73.225 22,73.5 21.757,73.743 20.107,73.743 19.975,73.875
NetCN1_2: CN1.2 R5.1 | length 12.2
  Top Layer 1 Signal w0.2: R5.1@16.1,69.75 16.42,69.91 16.5,69.95 ; 16.5,69.75 16.5,69.95 ; CN1.2@23.04,77.86 23.04,76.729 22.311,76 20.75,76 16.5,71.75 16.5,69.95
NetCN1_4: CN1.4 TP5.1 | length 2.8
  Top Layer 1 Signal w0.2: CN1.4@17.96,77.86 18,77.82 TP5.1@18,75.119
NetCN1_5: CN1.5 TP4.1 | length 2.8
  Top Layer 1 Signal w0.2: CN1.5@15.42,77.86 15.5,77.78 TP4.1@15.5,75.088
NetCN1_6: CN1.6 TP3.1 | length 2.8
  Top Layer 1 Signal w0.2: CN1.6@12.88,77.86 TP3.1@12.88,80.695
NetCN2_3: CN2.3 TP2.1 | length 3.1
  Top Layer 1 Signal w0.15: CN2.3@16.94,29.6 17,29.54 TP2.1@17,26.5
NetCN2_4: CN2.4 R2.2 | length 13.8
  Top Layer 1 Signal w0.2: v1(21.5,38.5) 23.525,38.5 24.5,39.475 R2.2@24.5,40.15
  Bottom Layer 4 Signal w0.2: CN2.4@19.48,29.6 21.5,31.62 v1(21.5,38.5)
NetCN2_5: CN2.5 JP1.2 | length 4.9
  Bottom Layer 4 Signal w0.45: CN2.5@22.02,29.6 22.02,31.54 JP1.2@23.98,33.5 ; JP1.2@23.878,33.553 JP1.2@23.98,33.75
NetCN2_8: CN2.8 TP6.1 | length 3.4
  Top Layer 1 Signal w0.2: TP6.1@29,26.5 29,28.779 29.64,29.419 CN2.8@29.64,29.6
NetCN3_1: CN3.1 TP17.1 | length 2.4
  Top Layer 1 Signal w0.2: CN3.1@47.42,77.86 47.42,79.55 cw(c47.62,79.55) 47.42,79.559 TP17.1@47.45,80.25
NetCN3_2: CN3.2 TP16.1 | length 2.4
  Top Layer 1 Signal w0.2: CN3.2@44.88,77.86 44.88,79.55 cw(c45.08,79.55) 44.881,79.57 TP16.1@44.95,80.25
NetCN3_4: CN3.4 TP15.1 | length 2.8
  Top Layer 1 Signal w0.2: TP15.1@39.8,75.096 CN3.4@39.8,77.86
NetCN3_5: CN3.5 TP14.1 | length 2.8
  Top Layer 1 Signal w0.2: TP14.1@37.26,75.096 CN3.5@37.26,77.86
NetCN3_6: CN3.6 TP12.1 | length 2.7
  Top Layer 1 Signal w0.2: TP12.1@34.72,75.114 CN3.6@34.72,77.86
NetCN3_7: CN3.7 TP10.1 | length 2.8
  Top Layer 1 Signal w0.2: TP10.1@32.18,75.105 CN3.7@32.18,77.86
NetCN3_8: CN3.8 TP8.1 | length 2.9
  Top Layer 1 Signal w0.2: CN3.8@29.64,77.86 29.64,77.454 30,77.094 TP8.1@30,75.078
NetCN4_1: CN4.1 TP7.1 | length 3.2
  Top Layer 1 Signal w0.2: TP7.1@34.5,26.5 34.5,26.597 34.72,26.817 CN4.1@34.72,29.6
NetCN4_2: CN4.2 TP9.1 | length 3.2
  Top Layer 1 Signal w0.2: TP9.1@37.038,26.462 37.038,26.557 37.26,26.779 CN4.2@37.26,29.6
NetCN4_3: CN4.3 TP11.1 | length 3.2
  Top Layer 1 Signal w0.2: TP11.1@39.5,26.5 39.5,28.733 39.513,28.746 39.513,29.313 CN4.3@39.8,29.6
NetCN4_4: CN4.4 TP13.1 | length 3.2
  Top Layer 1 Signal w0.2: TP13.1@42,26.5 42,28.854 42.34,29.194 CN4.4@42.34,29.6
NetCN7_A8: CN7.A8 TP19.1 | length 4.1
  Top Layer 1 Signal w0.2: TP19.1@37,42.5 38.418,42.5 38.535,42.383 38.535,41.035 38.818,40.752 39.588,40.752 CN7.A8@39.59,40.75
NetCN7_B8: CN7.B8 TP21.1 | length 10.9
  Top Layer 1 Signal w0.2: CN7.B8@41.55,39.2 45.6,43.25 48,43.25 48.75,44 TP21.1@48.75,45.75
NetL1_2: L1.2 U7.5 | length 2
  Top Layer 1 Signal w0.45: U7.5@19.95,82.15 21.85,82.15 L1.2@21.95,82.25
NetL2_2: L2.2 U11.5 | length 2.1
  Top Layer 1 Signal w0.45: U11.5@40.7,82.15 42.55,82.15 L2.2@42.7,82
NetL3_2: L3.2 U14.5 | length 1.7
  Top Layer 1 Signal w0.45: U14.5@43.1,53.7 44.6,53.7 L3.2@44.75,53.55
NetLD1_1: LD1.1 R16.1 | length 2.9
  Top Layer 1 Signal w0.2: LD1.1@3.5,34.5 R16.1@6.375,34.5
NetLD2_1: LD2.1 R21.1 | length 1.8
  Top Layer 1 Signal w0.45: R21.1@45.7,33.75 LD2.1@47.5,33.75
NetQ1_1: Q1.1 R34.1 | length 2.4
  Top Layer 1 Signal w0.15: Q1.1@12.6,18.05 12.6,17.15 12.75,17 13.25,17 13.401,16.849 R34.1@13.401,16.285
NetR1_2: R1.2 U1.1 | length 1.6
  Top Layer 1 Signal w0.45: U1.1@43.95,49.25 R1.2@45.55,49.25
NetR4_2: R4.2 R6.2 R33.1 | length 2.6
  Top Layer 1 Signal w0.15: R6.2@9.4,25.752 9.4,26.102 9.548,26.25 9.6,26.25 ; R4.2@9.4,26.8 9.4,26.45 9.6,26.25 ; R33.1@11,26.25 9.6,26.25
NetR7_2: R7.2 U2.3 | length 2.2
  Top Layer 1 Signal w0.45: R7.2@27.25,45.8 27.27,45.8 27.3,45.77 U2.3@27.3,43.675
NetR22_2: R22.2 R28.1 U5.11 | length 13.3
  Top Layer 1 Signal w0.2: R28.1@23.65,24 R22.2@21.85,24 21.85,23.35 21.6,23.1 20.837,23.1 20.587,22.85 20.587,17.435 21.091,16.932 23.124,16.932 23.281,16.775 U5.11@24.315,16.775
NetR54_1: R54.1 U10.35 | length 4.7
  Top Layer 1 Signal w0.2: R54.1@21.2,69.5 22,69.5 22.25,69.75 24,69.75 24.275,69.475 U10.35@25.7,69.475
NetR55_1: R55.1 U10.5 | length 6.4
  Top Layer 1 Signal w0.2: R55.1@26.25,61.45 26.243,61.457 26.243,64.128 26.511,64.396 27.646,64.396 28.4,65.15 U10.5@28.4,66.275
NetR56_2: R56.2 U10.7 | length 1.7
  Top Layer 1 Signal w0.25: U10.7@29.4,66.275 29.4,65.4 29.75,65.05 R56.2@29.75,64.7
NetTP1_1: TP1.1 U1.3 | length 2.4
  Top Layer 1 Signal w0.45: TP1.1@40.25,50 41.75,50 42.05,49.7 U1.3@42.05,49.25
NetTP24_1: TP24.1 U14.3 | length 1.8
  Top Layer 1 Signal w0.45: TP24.1@39.088,51.75 40.85,51.75 U14.3@40.9,51.8
OC13B_6: R49.1 U10.13 | length 4.9
  Top Layer 1 Signal w0.2: U10.13@31.6,67.975 34.275,67.975 34.75,67.5 35.2,67.5 35.7,68 R49.1@36.05,68
OC14B_6: R48.1 U10.17 | length 4.9
  Top Layer 1 Signal w0.2: U10.17@31.6,69.975 33.143,69.975 34.168,71 R48.1@36.05,71
PPON3B_6: R42.2 U10.12 | length 4.6
  Top Layer 1 Signal w0.2: U10.12@31.6,67.475 33.525,67.475 34,67 R42.2@36.05,67
PPON4B_6: R43.2 U10.16 | length 4.7
  Top Layer 1 Signal w0.2: U10.16@31.6,69.475 33.35,69.475 33.878,70.003 R43.2@36.054,70.003
PW_H1_EN_6_N: R41.1 U7.4 U10.30 | length 16.7
  Top Layer 1 Signal w0.2: U7.4@18.05,82.15 18.6,82.15 v1(18.75,82) ; v1(25.2,74.95) 25.2,74.3 R41.1@25.2,73.75 25.2,72.913 25.763,72.35 25.763,72.342 25.88,72.225 U10.30@26.4,72.225
  Layer 3 w0.2: v1(18.75,82) 18.702,81.952 18.702,81.775 18.697,81.77 18.697,80.649 18.615,80.567 18.615,79.385 19.238,78.762 19.238,76.46 19.698,76 24.15,76 v1(25.2,74.95)
PW_H1_OC_6_N: R53.1 U7.3 U10.1 | length 36.6
  Top Layer 1 Signal w0.2: v1(17,84.25) 17.95,84.25 U7.3@18.05,84.35 ; R53.1@22.7,65.25 23.25,65.25 v1(23.5,65.5) 24.673,65.5 25.398,66.225 U10.1@26.4,66.225
  Bottom Layer 4 Signal w0.2: v1(17,84.25) 17,84.211 16.797,84.008 16.797,80.774 16.669,80.647 16.669,79.534 16.497,79.362 16.497,74.753 18.25,73 18.25,61.75 18.75,61.25 20.5,61.25 21,61.75 21,63 v1(23.5,65.5)
PW_H2_EN_6_N: R40.1 U10.9 U11.4 | length 36.2
  Top Layer 1 Signal w0.2: R40.1@29.475,60.7 29.475,61.483 29.592,61.6 29.6,61.6 v1(30.25,62.25) 30.654,62.654 30.654,65.346 30.4,65.6 U10.9@30.4,66.275 ; v1(33.75,64.75) 37.5,64.75 38.827,66.077 38.827,72.577 41,74.75 41,78.75 40.75,79 39.5,79 38.8,79.7 U11.4@38.8,82.15
  Layer 3 w0.2: v1(30.25,62.25) 30.25,63.837 31.434,65.021 32.346,65.021 32.453,65.129 33.049,65.129 33.418,64.76 33.74,64.76 v1(33.75,64.75)
PW_H2_OC_6_N: R50.1 U10.10 U11.3 | length 33.1
  Top Layer 1 Signal w0.2: R50.1@30.5,60.7 30.5,61.5 31.073,62.073 31.073,65.389 30.9,65.562 U10.10@30.9,66.099 ; U10.10@30.9,66.225 U10.10@30.9,66.099 ; U11.3@38.8,84.35 38.8,83.367 38.683,83.25 38.25,83.25 38,83 38,79.5 38.5,79 38.5,66.25 37.5,65.25 34,65.25 33.173,66.077 32.618,66.077 32.614,66.074 30.925,66.074 U10.10@30.9,66.099
RF_EN_1V8: R3.2 R33.2 U4.H1 | length 31.7
  Top Layer 1 Signal w0.15: R33.2@12.1,26.25 14,26.25 14.2,26.05 14.2,10.85 14.2,8.277 19.255,3.223 23.631,3.223 23.704,3.15 23.748,3.15 23.798,3.1 U4.H1@23.825,3.1
RF_EN_3V3_4: CN1.3 R4.1 | length 59.5
  Top Layer 1 Signal w0.2: R4.1@9.4,27.7 9.4,36.68 9.2,36.88 9.2,72.7 10.25,73.75 18,73.75 20.5,76.25 CN1.3@20.5,77.86
RX_D2_3V3_4: CN3.3 JP4.1 | length 44
  Layer 3 w0.2: v1(17.5,72) 17.568,72 17.693,72.125 17.699,72.125 20.012,74.438 25.327,74.438 25.54,74.651 27.134,74.651 27.159,74.627 27.831,74.627 28.291,75.087 40.773,75.087 42.34,76.653 CN3.3@42.34,77.86
  Bottom Layer 4 Signal w0.2: v1(17.5,72) 15.75,70.25 15.75,61.25 16.235,60.765 18.275,60.765 JP4.1@19.54,59.5
RX_GPIO1_1V8: R37.1 U3.16 U4.D1 | length 51.3
  Top Layer 1 Signal w0.15: v1(18.75,40.75) v1(20.5,40.75) ; v1(19,27.25) 19.533,26.717 19.533,14.808 17.993,13.267 R37.1@17.993,11.5 17.993,6.052 19.713,4.331 23.393,4.331 23.689,4.627 23.725,4.627 23.798,4.7 U4.D1@23.825,4.7 ; v1(20.5,46) 20.575,46.075 U3.16@22.05,46.075
  Bottom Layer 4 Signal w0.15: v1(18.75,40.75) 18.75,38.791 18.298,38.339 18.298,27.952 v1(19,27.25) ; v1(20.5,40.75) 20.481,44.64 ccw(c20.331,44.639) 20.48,44.662 cw(c20.902,44.725) 20.479,44.785 ccw(c20.331,44.805) 20.481,44.806 20.475,45.918 cw(c20.625,45.918) v1(20.5,46)
RX_GPIO1_3V3_4: JP4.2 R8.2 R58.1 U3.5 | length 18.4
  Top Layer 1 Signal w0.2: U3.5@16.45,46.075 v1(18,46.075) ; v1(16.75,56.25) R58.1@16.75,55.5 16.75,53.9 R8.2@16.9,53.75
  Layer 3 w0.2: v1(16.75,56.25) 16.75,59.25 JP4.2@17,59.5
  Bottom Layer 4 Signal w0.2: v1(16.75,56.25) 16.75,52.775 18.277,51.248 18.277,46.365 18,46.088 v1(18,46.075)
SCL_1V8: JP5.1 R25.1 R26.1 U3.2 | length 39.5
  Top Layer 1 Signal w0.15: v1(14.25,41.5) v1(19.5,41.5) ; R25.1@17.25,19.202 v1(17.25,19.75) R26.1@17.25,20.75
  Top Layer 1 Signal w0.2: v1(14.25,48) 14.275,48.025 U3.2@16.45,48.025
  Layer 3 w0.15: v1(17.25,19.75) 17.25,20.128 19.533,22.411 19.533,27.644 20.717,28.828 20.717,31.725 21.09,32.097 21.09,35.45 JP5.1@19.54,37
  Bottom Layer 4 Signal w0.15: v1(14.25,41.5) v1(14.25,48) ; v1(19.5,41.5) 19.5,37.04 JP5.1@19.54,37
SCL_D15_3V3_4: CN1.10 R11.1 U3.19 | length 48.5
  Top Layer 1 Signal w0.2: R11.1@2.72,74.95 CN1.10@2.72,77.86 ; v1(14,54.2) 15.85,52.35 v1(19.425,52.35) ; v1(20,48) 20.025,48.025 U3.19@22.05,48.025
  Bottom Layer 4 Signal w0.2: CN1.10@2.72,77.86 4.555,76.025 12.038,76.025 12.75,75.313 12.75,55.45 v1(14,54.2) ; v1(19.425,52.35) 19.43,52.35 20,51.78 v1(20,48)
SCL_GPIO2_1V8: JP5.2 R36.1 U4.K1 | length 51.8
  Top Layer 1 Signal w0.15: v1(8.608,34.004) 8.608,12.917 9.55,11.975 R36.1@9.55,11.5 9.55,11.025 9.825,10.75 10.928,10.75 19.009,2.669 23.304,2.669 23.653,2.319 23.806,2.319 U4.K1@23.825,2.3 ; v1(17,35.45) JP5.2@17,37
  Bottom Layer 4 Signal w0.15: v1(8.608,34.004) 10.053,35.45 v1(17,35.45)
